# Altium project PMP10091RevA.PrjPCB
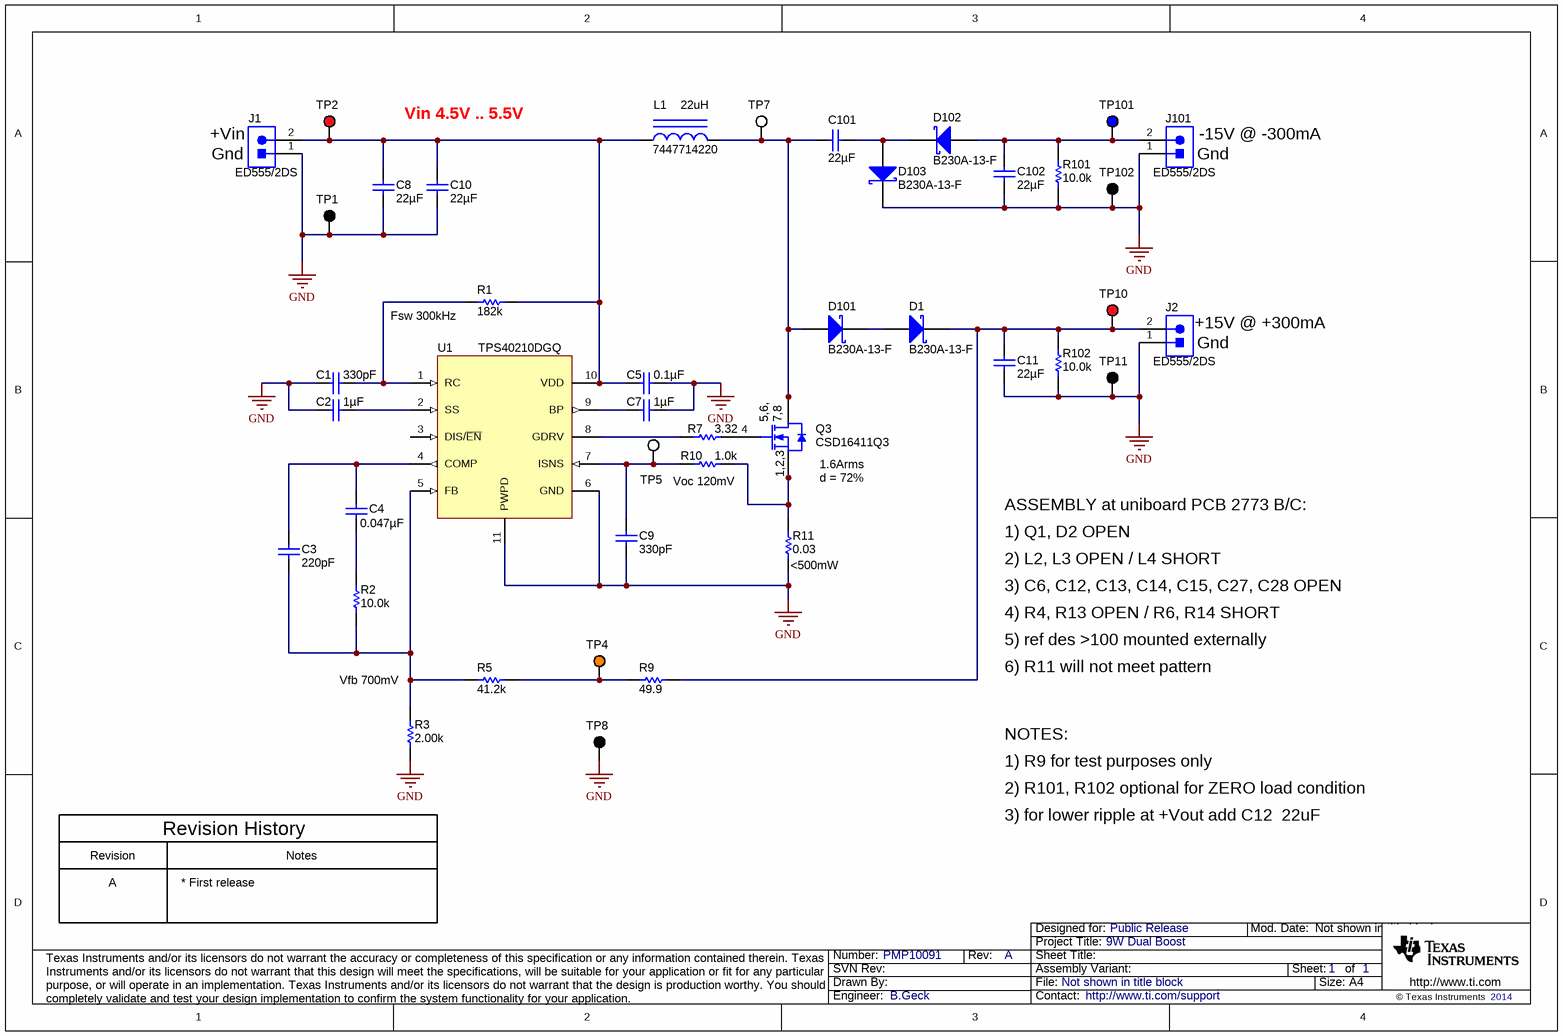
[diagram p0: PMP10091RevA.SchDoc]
CopyrightYear: 2014; PCB_Layout: B.Geck; PCB_Rev: A; PRJ_Customer: Public Release; PRJ_Engineer: B.Geck; PRJ_Number: PMP10091; PRJ_Title: 9W Dual Boost; SCH_Rev: A; TechSupport: http://www.ti.com/support
1 sheet, 42 parts. Net scope: global (net labels, ports and power ports of the same name join across sheets).

## Sheet PMP10091RevA.SchDoc
size A4; Date: Not shown in title block; ApprovedBy: Not shown in title block; CheckedBy: Not shown in title block; Author: Not shown in title block; CompanyName: Not shown in title block; Engineer: Not shown in title block; Organization: Not shown in title block; Address1: Not shown in title block; Address2: Not shown in title block; Address3: Not shown in title block; Address4: Not shown in title block; DocumentNumber: 1; Revision: Use project parameter SCH_Rev; SheetNumber: 1; SheetTotal: 1; PageSetup: Record=PageOptions¦CenterHorizontal=True¦CenterVertical=True¦PrintScale=0.70¦XCorrection=1.00¦YCorrection=1.00¦PrintKind=0¦BorderSize=5000000¦LeftOffset=0¦BottomOffset=0¦Orientation=2¦PaperLength=1000¦PaperWidth=1000¦Scale=100¦PaperSource=15¦PrintQuality=600¦MediaType=1¦DitherType=10¦PaperKind=A4¦PrintScaleMode=1

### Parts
C1  ValueDisplayed: 330pF  [0603]  (hidden comment: GRM188R71H331KA01D)
C2  ValueDisplayed: 1µF  [0603]  (hidden comment: GRM188R71E105KA12D)
C3  ValueDisplayed: 220pF  [0603]  (hidden comment: GRM188R71H221KA01D)
C4  ValueDisplayed: 0.047µF  [0603]  (hidden comment: GRM188R71E473KA01D)
C5  ValueDisplayed: 0.1µF  [0603]  (hidden comment: GRM188R71H104KA93D)
C7  ValueDisplayed: 1µF  [0603]  (hidden comment: GRM188R71E105KA12D)
C8  ValueDisplayed: 22µF  [1210]  (hidden comment: GRM32ER71E226KE15L)
C9  ValueDisplayed: 330pF  [0603]  (hidden comment: GRM188R71H331KA01D)
C10  ValueDisplayed: 22µF  [1210]  (hidden comment: GRM32ER71E226KE15L)
C11  ValueDisplayed: 22µF  [1210]  (hidden comment: GRM32ER71E226KE15L)
C101  ValueDisplayed: 22µF  [1210]  (hidden comment: GRM32ER71E226KE15L)
C102  ValueDisplayed: 22µF  [1210]  (hidden comment: GRM32ER71E226KE15L)
D1  B230A-13-F  [SMA]
D101  B230A-13-F  [SMA]
D102  B230A-13-F  [SMA]
D103  B230A-13-F  [SMA]
J1  ED555/2DS  [TERM_BLK_ED555-2DS]
J2  ED555/2DS  [TERM_BLK_ED555-2DS]
J101  ED555/2DS  [TERM_BLK_ED555-2DS]
L1  7447714220  value 22uH  [WE-PD-1050]
Q3  CSD16411Q3  [TRANS_NexFET_Q3]
R1  value 182k  [0603]  (hidden comment: CRCW0603182KFKEA)
R2  value 10.0k  [0603]  (hidden comment: CRCW060310K0FKEA)
R3  value 2.00k  [0603]  (hidden comment: CRCW06032K00FKEA)
R5  value 41.2k  [0603]  (hidden comment: CRCW060341K2FKEA)
R7  value 3.32  [0603]  (hidden comment: CRCW06033R32FKEA)
R9  value 49.9  [0603]  (hidden comment: CRCW060349R9FKEA)
R10  value 1.0k  [0603]  (hidden comment: CRCW06031K00JNEA)
R11  value 0.03  [2010M]  (hidden comment: CSRN2010FK30L0)
R101  value 10.0k  [0603]  (hidden comment: CRCW060310K0FKEA)
R102  value 10.0k  [0603]  (hidden comment: CRCW060310K0FKEA)
TP1  5001  [Keystone5001]  (value not drawn)
TP2  5000  [Keystone5000]  (value not drawn)
TP4  5003  [Keystone5003]  (value not drawn)
TP5  5002  [Keystone5002]  (value not drawn)
TP7  5002  [Keystone5002]  (value not drawn)
TP8  5001  [Keystone5001]  (value not drawn)
TP10  5000  [Keystone5000]  (value not drawn)
TP11  5001  [Keystone5001]  (value not drawn)
TP101  5117  [Keystone5117]  (value not drawn)
TP102  5001  [Keystone5001]  (value not drawn)
U1  TPS40210DGQ  [DGQ0010D_N]

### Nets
GND: C1.1 C2.1 C5.2 C7.2 C8.2 C9.2 C10.2 C11.2 C102.2 D103.1(K) J1.1 J2.1 J101.1 R3.1 R11.1 R101.1 R102.1 TP1.1 TP8.1 TP11.1 TP102.1 U1.6(GND) U1.11(PWPD)
NetC1_2: C1.2 R1.1 U1.1(RC)
NetC2_2: C2.2 U1.2(SS)
NetC3_1: C3.1 C4.1 U1.4(COMP)
NetC3_2: C3.2 R2.1 R3.2 R5.1 U1.5(FB)
NetC4_2: C4.2 R2.2
NetC5_1: C5.1 C8.1 C10.1 J1.2 L1.1 R1.2 TP2.1 U1.10(VDD)
NetC7_1: C7.1 U1.9(BP)
NetC9_1: C9.1 R10.1 TP5.1 U1.7(ISNS)
NetC11_1: C11.1 D1.1(K) J2.2 R9.2 R102.2 TP10.1
NetC101_1: C101.1 D101.2(A) L1.2 Q3.5(D) Q3.6(D) Q3.7(D) Q3.8(D) TP7.1
NetC101_2: C101.2 D102.1(K) D103.2(A)
NetC102_1: C102.1 D102.2(A) J101.2 R101.2 TP101.1
NetD1_2: D1.2(A) D101.1(K)
NetQ3_1: Q3.1(S) Q3.2(S) Q3.3(S) R10.2 R11.2
NetQ3_4: Q3.4(G) R7.2
NetR5_2: R5.2 R9.1 TP4.1
NetR7_1: R7.1 U1.8(GDRV)

Not connected (* = marked no-connect by the designer): U1 3(DIS/~{EN})

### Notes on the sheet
- Vin 4.5V .. 5.5V
- (near J1) +Vin
- (near J1) Gnd
- (near J101) Gnd
- (near J101) -15V @ -300mA
- (near R1) Fsw 300kHz
- (near J2) Gnd
- (near J2) +15V @ +300mA
- (near R10) Voc 120mV
- (near Q3) 1.6Arms
- d = 72%
- ASSEMBLY at uniboard PCB 2773 B/C:
- (near R11) <500mW
- 1) Q1, D2 OPEN
- 2) L2, L3 OPEN / L4 SHORT
- 3) C6, C12, C13, C14, C15, C27, C28 OPEN
- 4) R4, R13 OPEN / R6, R14 SHORT
- 5) ref des >100 mounted externally
- (near R3) Vfb 700mV
- 6) R11 will not meet pattern
- NOTES:
- 1) R9 for test purposes only
- 2) R101, R102 optional for ZERO load condition
- Revision
- Revision History
- Notes
- 3) for lower ripple at +Vout add C12  22uF
- A
- * First release

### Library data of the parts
C1 C9 = GRM188R71H331KA01D: CAP, CERM, 330pF, 50V, +/-10%, X7R, 0603; Manufacturer: MuRata; Polarized: N; CompType: Capacitor; U/M: EA; Cap_F: 0.00000000033; Tolerance_%: 10; Value1: Unknown; VDC_V: 50; TaMin_C: -55; TaMax_C: 125
C2 C7 = GRM188R71E105KA12D: CAP, CERM, 1uF, 25V, +/-10%, X7R, 0603; Manufacturer: MuRata; Polarized: N; CompType: Capacitor; U/M: EA; Cap_F: 0.000001; Tolerance_%: 10; Value1: Unknown; VDC_V: 25; TaMin_C: -55; TaMax_C: 125
C3 = GRM188R71H221KA01D: CAP, CERM, 220pF, 50V, +/-10%, X7R, 0603; Manufacturer: MuRata; Polarized: N; CompType: Capacitor; U/M: EA; Cap_F: 0.00000000022; Tolerance_%: 10; Value1: Unknown; VDC_V: 50; TaMin_C: -55; TaMax_C: 125
C4 = GRM188R71E473KA01D: CAP, CERM, 0.047uF, 25V, +/-10%, X7R, 0603; Manufacturer: MuRata; Polarized: N; CompType: Capacitor; U/M: EA; Cap_F: 0.000000047; Tolerance_%: 10; Value1: Unknown; VDC_V: 25; TaMin_C: -55; TaMax_C: 125
C5 = GRM188R71H104KA93D: CAP, CERM, 0.1uF, 50V, +/-10%, X7R, 0603; Manufacturer: MuRata; Polarized: N; CompType: Capacitor; U/M: EA; Cap_F: 0.0000001; Tolerance_%: 10; Value1: Unknown; VDC_V: 50; TaMin_C: -55; TaMax_C: 125
C8 C10 C11 C101 C102 = GRM32ER71E226KE15L: CAP, CERM, 22uF, 25V, +/-10%, X7R, 1210; Manufacturer: MuRata; Polarized: N; CompType: Capacitor; U/M: EA; Cap_F: 0.000022; Tolerance_%: 10; Value1: Unknown; VDC_V: 25; TaMin_C: -55; TaMax_C: 125
D1 D101-D103 = B230A-13-F: Diode, Schottky, 30V, 2A, SMA; Manufacturer: Diodes Inc.; U/M: EA; Vf_V: 0.5; Value2: 0.5V; Io_A: 2; Vr_V: 30; TJmax_C: 150; RJC_CperW: 20
J1 J2 J101 = ED555/2DS: Terminal Block, 6A, 3.5mm Pitch, 2-Pos, TH; Manufacturer: On-Shore Technology; SymbolCreator: a0412235; CompType: Connector; U/M: EA
L1 = 7447714220: Inductor, Shielded Drum Core, Ferrite, 22uH, 3A, 0.042 ohm, SMD; Manufacturer: Wurth Elektronik eiSos; Ind_H: 22.0E-6; ValueDisplayed: 22µH; Imax_A: 3; Irms: 3A @ 40C rise; Isat: 3.6A @ 10% inductance drop; DCR_ohm: 0.042
Q3 = CSD16411Q3: MOSFET, N-CH, 25V, 56A, SON 3.3x3.3mm; Manufacturer: Texas Instruments; Alternate Manufacturer: None; U/M: EA; ChType: N; VdsMax_V: 25; Value1: 0.012 ohm; Rdson45_Ohm: 0.012; Value2: 2.9 nC; QgTyp_nC: 2.9; Vgs_V: 16; IdsMax_A: 56
R1 = CRCW0603182KFKEA: RES, 182k ohm, 1%, 0.1W, 0603; Manufacturer: Vishay-Dale; CompType: Resistor; Res_ohm: 182000; Tolerance_%: 1; Power_W: 0.1; VDC_V: 75; TempCo: 100 ppm/C; EIA_Code: E96; U/M: EA
R2 R101 R102 = CRCW060310K0FKEA: RES, 10.0k ohm, 1%, 0.1W, 0603; Manufacturer: Vishay-Dale; CompType: Resistor; Res_ohm: 10000; Value_Code: 10k0; Tolerance_%: 1; Power_W: 0.1; VDC_V: 75; TempCo: 100 ppm/C; EIA_Code: E96; U/M: EA
R3 = CRCW06032K00FKEA: RES, 2.00k ohm, 1%, 0.1W, 0603; Manufacturer: Vishay-Dale; CompType: Resistor; Res_ohm: 2000; Value_Code: 2k00; Tolerance_%: 1; Power_W: 0.1; VDC_V: 75; TempCo: 100 ppm/C; EIA_Code: E96; U/M: EA
R5 = CRCW060341K2FKEA: RES, 41.2k ohm, 1%, 0.1W, 0603; Manufacturer: Vishay-Dale; CompType: Resistor; Res_ohm: 41200; Value_Code: 41k2; Tolerance_%: 1; Power_W: 0.1; VDC_V: 75; TempCo: 100 ppm/C; EIA_Code: E96; U/M: EA
R7 = CRCW06033R32FKEA: RES, 3.32 ohm, 1%, 0.1W, 0603; Manufacturer: Vishay-Dale; CompType: Resistor; Value_Code: 3R32; Tolerance_%: 1; Power_W: 0.1; VDC_V: 75; TempCo: 100 ppm/C; EIA_Code: E96; U/M: EA
R9 = CRCW060349R9FKEA: RES, 49.9 ohm, 1%, 0.1W, 0603; Manufacturer: Vishay-Dale; CompType: Resistor; Value_Code: 49R9; Tolerance_%: 1; Power_W: 0.1; VDC_V: 75; TempCo: 100 ppm/C; EIA_Code: E96; U/M: EA
R10 = CRCW06031K00JNEA: RES, 1.0k ohm, 5%, 0.1W, 0603; Manufacturer: Vishay-Dale; CompType: Resistor; Res_ohm: 1000; Value_Code: 1k00; Tolerance_%: 5; Power_W: 0.1; VDC_V: 75; TempCo: 200 ppm/C; EIA_Code: E24; U/M: EA
R11 = CSRN2010FK30L0: RES, 0.03 ohm, 1%, 1W, 2010; Manufacturer: Stackpole Electronics Inc; CompType: Resistor; Value_Code: R030; Tolerance_%: 1; TempCo: 250 ppm/C; EIA_Code: E96; U/M: EA
TP1 TP8 TP11 TP102 = 5001: Test Point, Miniature, Black, TH; Manufacturer: Keystone; CompType: Test Point Loop; U/M: EA
TP2 TP10 = 5000: Test Point, Miniature, Red, TH; Manufacturer: Keystone; CompType: Test Point Loop; U/M: EA
TP4 = 5003: Test Point, Miniature, Orange, TH; Manufacturer: Keystone; CompType: Test Point Loop; U/M: EA
TP5 TP7 = 5002: Test Point, Miniature, White, TH; Manufacturer: Keystone; CompType: Test Point Loop; U/M: EA
TP101 = 5117: Test Point, Miniature, Blue, TH; Manufacturer: Keystone; CompType: Test Point Loop; U/M: EA
U1 = TPS40210DGQ: 4.5-V TO 52-V INPUT CURRENT MODE BOOST CONTROLLER, DGQ0010D; Alternate Manufacturer: None; Manufacturer: Texas Instruments; SymbolCreator: a0412235; CompType: IC; U/M: EA

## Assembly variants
001: all parts fitted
